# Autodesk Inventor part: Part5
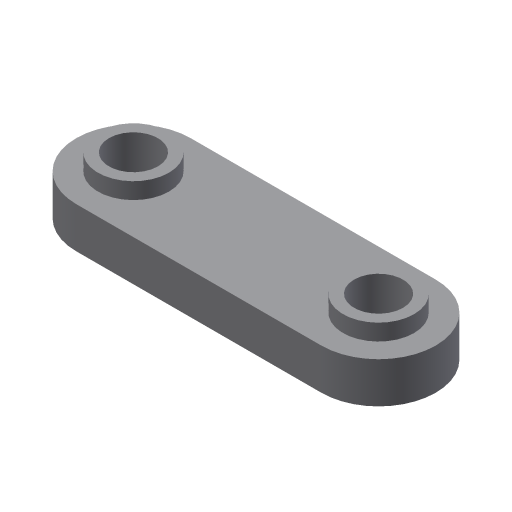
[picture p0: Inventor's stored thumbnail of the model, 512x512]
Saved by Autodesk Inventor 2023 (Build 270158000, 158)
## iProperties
Created: 2002-01
Part Number: Part5
Document SubType Name: Modeling
Designer: ***
Density: 1 g/cm^3
Material: Generic
Appearance: Default
Control State: 0
Master: False
Checked Out: False
Shininess: 77.0
Length Units: 11269
Angle Units: 11279
Time Units: 11290
Mass Units: 11283
Length Display Precision: 3
Angle Display Precision: 2
Density: 0.0
Volumn: 0.0
Area: 0.0
PropertySet Name: Model Information
Author: ***
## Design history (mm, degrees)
sketch "Sketch1"
  geometry: L1 (-33.118, 12.346)-(26.882, 12.361); L2 (-33.111, -15.654)-(26.889, -15.639); C1 r 6 at (-33.114, -1.654); C2 r 6 at (26.886, -1.639); A1 r 14 centre (-33.114, -1.654) between (-33.118, 12.346) and (-33.111, -15.654); A2 r 14 centre (26.886, -1.639) between (26.889, -15.639) and (26.882, 12.361)
  constraints: 4 centre point, 4 end point, 4 point on circle, 4 tangent, 2 coincident, 2 equal radius
  dimensions: "d0" = 60 distance of L1.start L1.end; "d1" = 14 radius of A1; "d2" = 12 diameter of C1
extrude "Extrusion1" new body sketch "Sketch1" distance "d3" = 10; taper "d4" = 0 deg
sketch "Sketch2"
  geometry: C1 r 6 at (26.886, -1.639) reference; C2 r 6 at (-33.114, -1.654) reference; C3 r 8.694 at (-33.114, -1.654); C4 r 8.694 at (26.886, -1.639)
  constraints: 2 centre point, 2 coincident, 1 equal radius
extrude "Extrusion2" join sketch "Sketch2" distance "d5" = 4; taper "d6" = 0 deg
body "Solid1"
